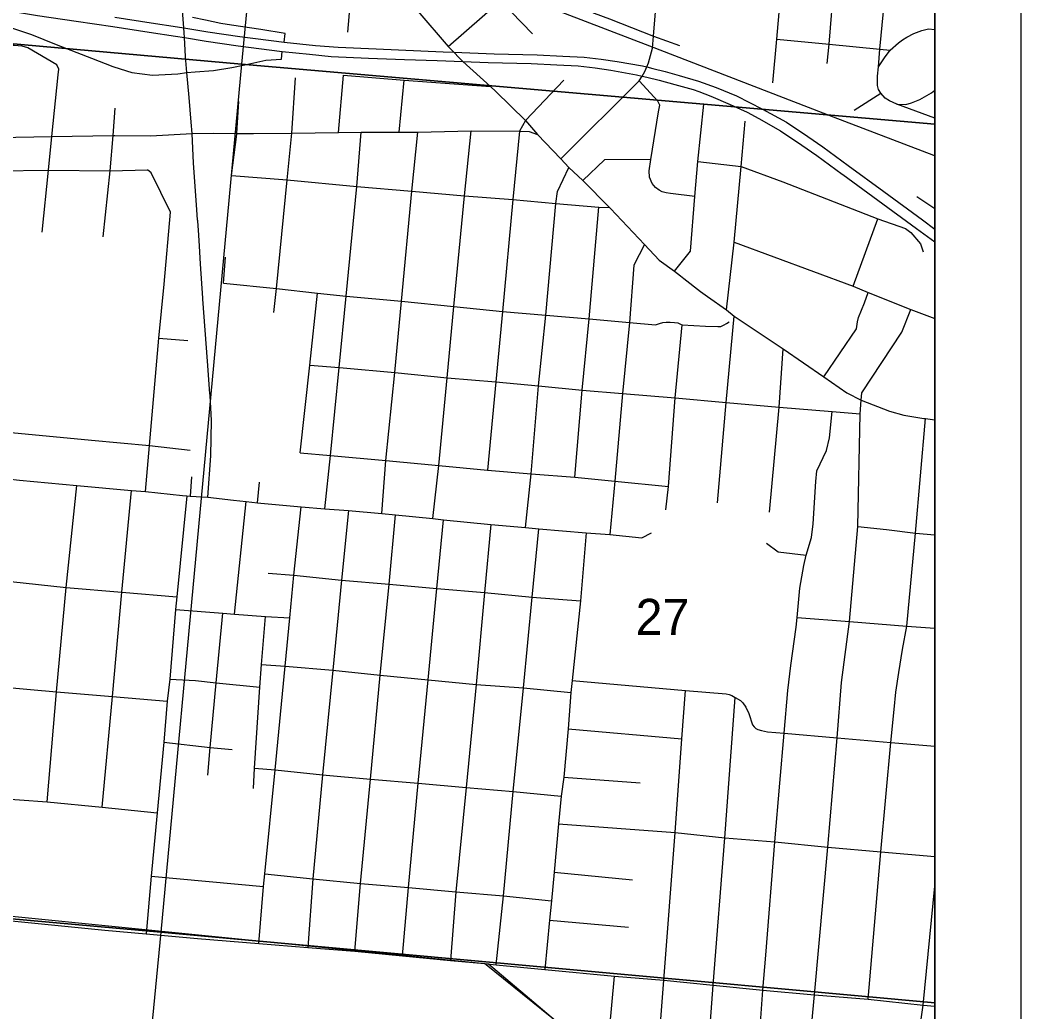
# Model space of a CAD drawing. Extents: x 0 to 34, y 0 to 22.
# Drawn here: x 7.838 to 9, y 16.794 to 17.945 of the extents above; entities that cross this region are included whole.
import ezdxf

# ---------------------------------------------------------------- set-up
doc = ezdxf.new("R2010")
doc.units = 0
for name, color, linetype in [('Default', 7, 'Continuous'), ('GM_X_City_Street', 7, 'Continuous'), ('GM_X_Interchange_Ramps', 7, 'Continuous'), ('GM_X_Rail_Line', 7, 'Continuous'), ('GM_X_Section', 7, 'Continuous'), ('GM_X_Section_Text', 7, 'Continuous'), ('GM_X_State_Route', 7, 'Continuous'), ('GM_X_Township_Road', 7, 'Continuous'), ('GM_X_US_Route', 7, 'Continuous'), ('SH_Data', 7, 'Continuous')]:
    doc.layers.add(name, color=color, linetype=linetype)

msp = doc.modelspace()

# ---------------------------------------------------------------- linework, layer by layer
at = {"layer": 'Default'}
for points in [[(8.9, 17.824), (8.9, 18.837), (8.1916, 18.9018), (8.0955, 17.8939)], [(8.9, 16.8048), (8.9, 17.824), (8.0955, 17.8939), (8.0016, 16.8868)], [(8.9, 15.7814), (8.9, 16.8048), (8.0016, 16.8868), (7.9035, 15.8736)]]:
    msp.add_lwpolyline(points, close=True, dxfattribs=at)
at = {"layer": 'GM_X_City_Street'}
for p, q in [((8.208, 17.8143), (8.2137, 17.8808)), ((8.2784, 17.815), (8.2841, 17.8753)), ((8.8063, 17.8402), (8.8375, 17.86)), ((8.0838, 17.7645), (8.0898, 17.8124)), ((8.293, 17.7464), (8.3, 17.815)), ((8.8792, 17.7402), (8.9, 17.7264)), ((8.8052, 17.636), (8.8337, 17.7144)), ((8.0746, 17.6398), (8.0767, 17.6697)), ((7.9994, 17.5759), (8.0332, 17.5733)), ((8.0372, 17.4151), (8.0357, 17.3925)), ((8.1138, 17.3849), (8.1161, 17.4089)), ((8.0874, 17.2557), (8.1006, 17.3863)), ((8.4745, 17.1225), (8.6063, 17.1111)), ((8.4693, 17.0668), (8.5579, 17.06)), ((8.7145, 16.9915), (8.7203, 17.0595)), ((8.7037, 16.8601), (8.7145, 16.9915)), ((7.9904, 16.9517), (8.1209, 16.9396)), ((8.4583, 16.9566), (8.5493, 16.9477)), ((8.8865, 16.8022), (8.9, 16.9403)), ((8.4529, 16.9008), (8.5445, 16.8926))]:
    msp.add_line(p, q, dxfattribs=at)
for points in [[(8.4658, 17.7839), (8.557, 17.8745), (8.5603, 17.8799), (8.5634, 17.8851), (8.5657, 17.8905), (8.5676, 17.8951), (8.5725, 17.9124), (8.5734, 17.9262), (8.5809, 18.0161), (8.5928, 18.1356), (8.5986, 18.1365), (8.6015, 18.1373), (8.6038, 18.1383), (8.6061, 18.1396), (8.6097, 18.1419), (8.612, 18.1444), (8.613, 18.1463), (8.6141, 18.1494), (8.6151, 18.1532), (8.6168, 18.164)], [(8.712, 17.8722), (8.7165, 17.9229), (8.7229, 17.994), (8.7276, 18.0443), (8.7323, 18.0974), (8.7371, 18.1527)], [(8.9, 17.8309), (8.8559, 17.8474), (8.8473, 17.851), (8.8424, 17.8541), (8.8375, 17.86), (8.8348, 17.8642), (8.8333, 17.8691), (8.8333, 17.8798), (8.8348, 17.8905), (8.836, 17.9113), (8.8432, 17.9829), (8.8457, 18.0185), (8.8462, 18.025), (8.8468, 18.0293), (8.8491, 18.0338), (8.8522, 18.038), (8.8567, 18.0417), (8.8624, 18.0448), (8.8734, 18.0465)], [(8.2186, 17.9307), (8.2215, 17.962), (8.2279, 18.0282)], [(8.032, 17.8842), (8.0305, 17.9026), (8.029, 17.9246), (8.0286, 17.9302), (8.0283, 17.936), (8.0274, 17.9511), (8.0268, 17.962), (8.0253, 17.9814), (8.023, 18.0144)], [(8.2373, 18.0182), (8.2468, 18.0082), (8.2986, 17.9567), (8.2999, 17.9553), (8.3352, 17.9144), (8.3416, 17.9076), (8.3479, 17.9009), (8.3524, 17.8968), (8.3843, 17.8677), (8.3905, 17.8621), (8.425, 17.8284), (8.4387, 17.812), (8.4658, 17.7839), (8.4754, 17.7739), (8.4916, 17.7589), (8.5224, 17.7275), (8.5237, 17.7263), (8.5629, 17.6847), (8.58, 17.6665), (8.598, 17.6535), (8.6049, 17.648)], [(8.7752, 17.8944), (8.7772, 17.9171), (8.7833, 17.9883)], [(8.3352, 17.9144), (8.3961, 17.9672), (8.4332, 17.9289)], [(8.4963, 17.959), (8.5045, 17.953), (8.5223, 17.9462), (8.5734, 17.9262), (8.6037, 17.9152)], [(7.8638, 17.6989), (7.8714, 17.7707), (7.8751, 17.8097), (7.8824, 17.8813), (7.8834, 17.8881), (7.8809, 17.893), (7.8472, 17.9126), (7.8408, 17.9145), (7.8315, 17.9155), (7.8271, 17.9155), (7.8227, 17.917), (7.8154, 17.9228), (7.8129, 17.9258)], [(8.8348, 17.8905), (8.8415, 17.901), (8.8483, 17.9099), (8.8577, 17.9184), (8.8623, 17.9218), (8.8675, 17.9252), (8.8758, 17.9294), (8.8848, 17.9328), (8.8926, 17.9346), (8.9, 17.9338)], [(8.7165, 17.9229), (8.7772, 17.9171), (8.836, 17.9113), (8.8483, 17.9099)], [(8.038, 17.8134), (8.037, 17.8264), (8.0347, 17.855), (8.032, 17.8842)], [(8.2137, 17.8808), (8.2841, 17.8753), (8.3843, 17.8677)], [(8.133, 17.6055), (8.1358, 17.6333), (8.1483, 17.7596), (8.1536, 17.8135), (8.158, 17.878)], [(8.4693, 17.875), (8.425, 17.8284), (8.4178, 17.8161), (8.4104, 17.7368), (8.3983, 17.6069), (8.3904, 17.5254), (8.381, 17.4229)], [(8.6216, 17.7404), (8.5933, 17.7435), (8.5883, 17.7443), (8.5837, 17.7455), (8.5802, 17.7474), (8.576, 17.7505), (8.5721, 17.7551), (8.569, 17.7628), (8.5686, 17.7698), (8.5705, 17.7833), (8.5794, 17.8386), (8.5808, 17.8461), (8.5787, 17.8509), (8.557, 17.8745)], [(8.8559, 17.8474), (8.8664, 17.847), (8.873, 17.849), (8.8827, 17.8529), (8.8961, 17.8604), (8.9, 17.8634)], [(8.0898, 17.8124), (8.0899, 17.8134), (8.0923, 17.8505)], [(8.598, 17.6535), (8.6164, 17.6766), (8.6216, 17.7404), (8.6251, 17.7807), (8.632, 17.8474)], [(7.9347, 17.6935), (7.9428, 17.7701), (7.9464, 17.8109), (7.9489, 17.8426)], [(8.6582, 17.6086), (8.667, 17.6874), (8.6753, 17.775), (8.6797, 17.8276)], [(7.7182, 17.8078), (7.7277, 17.808), (7.7409, 17.8083), (7.8054, 17.8088), (7.812, 17.8088), (7.8751, 17.8097), (7.9464, 17.8109), (7.9484, 17.8109)], [(7.9484, 17.8109), (7.9898, 17.8107), (8.038, 17.8134), (8.0634, 17.8135), (8.0899, 17.8134), (8.098, 17.8133)], [(8.0444, 17.713), (8.043, 17.7307), (8.0396, 17.779), (8.038, 17.8134)], [(8.098, 17.8133), (8.1091, 17.8132), (8.1536, 17.8135), (8.208, 17.8143), (8.2344, 17.8147), (8.2784, 17.815), (8.3, 17.815), (8.3617, 17.8163), (8.4178, 17.8161), (8.4291, 17.8158), (8.4387, 17.812)], [(8.2086, 17.5419), (8.2167, 17.6245), (8.2292, 17.7517), (8.2344, 17.8147)], [(8.3175, 17.3665), (8.3244, 17.428), (8.3342, 17.53), (8.3417, 17.6127), (8.3542, 17.7409), (8.3617, 17.8163)], [(8.5705, 17.7833), (8.5165, 17.7826), (8.4916, 17.7589)], [(8.6251, 17.7807), (8.6753, 17.775), (8.7236, 17.7571), (8.8337, 17.7144), (8.8658, 17.7031), (8.872, 17.6984), (8.8833, 17.6853), (8.8863, 17.6762)], [(7.1731, 17.6598), (7.207, 17.6858), (7.2406, 17.7105), (7.3207, 17.7132), (7.4116, 17.7144), (7.499, 17.7158), (7.568, 17.7076), (7.6318, 17.7023), (7.7067, 17.6964), (7.7185, 17.7023), (7.8124, 17.7701), (7.8714, 17.7707), (7.9428, 17.7701), (7.9864, 17.7713)], [(7.984, 17.3979), (7.9884, 17.4512), (7.9994, 17.5759), (8.0054, 17.6386), (8.0131, 17.722), (7.9904, 17.7676), (7.9864, 17.7713)], [(8.0838, 17.7645), (8.1483, 17.7596), (8.2292, 17.7517), (8.293, 17.7464), (8.3542, 17.7409), (8.4104, 17.7368), (8.4603, 17.732), (8.5101, 17.7279), (8.5224, 17.7275)], [(8.425, 17.3561), (8.4314, 17.4183), (8.44, 17.5207), (8.4486, 17.6027), (8.4603, 17.732), (8.4619, 17.7461), (8.4754, 17.7739)], [(8.2581, 17.3723), (8.263, 17.4341), (8.2733, 17.536), (8.2809, 17.6188), (8.293, 17.7464)], [(8.4821, 17.4146), (8.4908, 17.5155), (8.4988, 17.5982), (8.5101, 17.7279)], [(8.0465, 17.6826), (8.0457, 17.6953), (8.0445, 17.7121), (8.0444, 17.713)], [(8.0505, 17.6223), (8.0478, 17.662), (8.0465, 17.6826)], [(8.5629, 17.6847), (8.5507, 17.6604), (8.5457, 17.5939), (8.5376, 17.5118), (8.5286, 17.4101), (8.5227, 17.348)], [(8.667, 17.6874), (8.8052, 17.636), (8.8226, 17.629), (8.8723, 17.6093), (8.9, 17.5986)], [(8.6049, 17.648), (8.6088, 17.6449), (8.628, 17.63), (8.636, 17.6243)], [(8.0746, 17.6398), (8.1358, 17.6333), (8.1834, 17.6281), (8.2167, 17.6245), (8.2809, 17.6188), (8.3417, 17.6127), (8.3983, 17.6069), (8.4486, 17.6027), (8.4988, 17.5982), (8.5457, 17.5939), (8.5758, 17.5912), (8.5805, 17.5927), (8.5844, 17.5939), (8.5883, 17.5944), (8.5929, 17.5946), (8.5977, 17.5942), (8.6017, 17.5935), (8.6049, 17.5922), (8.6069, 17.5912), (8.6338, 17.5897), (8.6481, 17.5894), (8.6516, 17.5895), (8.6554, 17.5912), (8.6584, 17.5927), (8.6612, 17.595)], [(8.1634, 17.4428), (8.1746, 17.5445), (8.1834, 17.6281)], [(8.636, 17.6243), (8.6582, 17.6086), (8.6672, 17.6015), (8.6753, 17.596)], [(8.771, 17.5309), (8.8091, 17.5867), (8.8102, 17.595), (8.8115, 17.5998), (8.8182, 17.617), (8.8226, 17.629)], [(8.0587, 17.5116), (8.0559, 17.549), (8.0506, 17.6212), (8.0505, 17.6223)], [(8.6477, 17.3849), (8.658, 17.5013), (8.6672, 17.6015)], [(8.9, 16.4865), (8.8662, 16.4889), (8.8359, 16.4923), (8.7983, 16.5429), (8.7412, 16.6234), (8.751, 16.6985), (8.7551, 16.7564), (8.7604, 16.814), (8.776, 16.9853), (8.7868, 17.1123), (8.7916, 17.1766), (8.8011, 17.2471), (8.8108, 17.3575), (8.8134, 17.4882), (8.8144, 17.504), (8.8153, 17.5125), (8.8617, 17.5828), (8.8723, 17.6093)], [(8.5877, 17.3766), (8.591, 17.4037), (8.5986, 17.5068), (8.6069, 17.5912)], [(8.6753, 17.596), (8.724, 17.5635), (8.771, 17.5309), (8.7979, 17.5126), (8.8144, 17.504), (8.8475, 17.491), (8.8639, 17.4867), (8.8874, 17.4828)], [(8.708, 17.374), (8.7194, 17.4958), (8.724, 17.5635)], [(8.1746, 17.5445), (8.2086, 17.5419), (8.2135, 17.5414)], [(8.1921, 17.378), (8.1986, 17.4396), (8.2086, 17.5419)], [(8.2135, 17.5414), (8.2733, 17.536), (8.3342, 17.53), (8.3904, 17.5254), (8.44, 17.5207), (8.4908, 17.5155), (8.5376, 17.5118), (8.5986, 17.5068), (8.658, 17.5013), (8.7194, 17.4958), (8.7807, 17.4908), (8.8134, 17.4882)], [(8.0564, 17.3913), (8.0597, 17.4393), (8.0607, 17.4804), (8.0588, 17.5095), (8.0587, 17.5116)], [(7.613, 17.4851), (7.7167, 17.4762), (7.8282, 17.4663), (7.9213, 17.4577), (7.9884, 17.4512), (8.0357, 17.4461)], [(8.7203, 17.0595), (8.7252, 17.1178), (8.7295, 17.1671), (8.7327, 17.196), (8.7392, 17.2406), (8.7402, 17.2517), (8.7435, 17.2859), (8.7479, 17.3123), (8.7505, 17.324), (8.7567, 17.3445), (8.7588, 17.3606), (8.7618, 17.4097), (8.7632, 17.4221), (8.7742, 17.4455), (8.7779, 17.4602), (8.7807, 17.4908)], [(8.8226, 16.8089), (8.8373, 16.9799), (8.849, 17.1067), (8.8528, 17.145), (8.8548, 17.1654), (8.8584, 17.1881), (8.8624, 17.2149), (8.8677, 17.2419), (8.8775, 17.3498), (8.8893, 17.4825)], [(8.8874, 17.4828), (8.8893, 17.4825), (8.9, 17.481)], [(7.3271, 17.4595), (7.3398, 17.4568), (7.4144, 17.4515), (7.4756, 17.4469), (7.4803, 17.4464), (7.5437, 17.4399), (7.6073, 17.4333), (7.628, 17.4313), (7.695, 17.4246), (7.7123, 17.423), (7.7746, 17.417), (7.8046, 17.4146), (7.8242, 17.4125), (7.8376, 17.411), (7.9042, 17.4049), (7.9675, 17.3993), (7.984, 17.3979), (8.0267, 17.3935)], [(8.1634, 17.4428), (8.1986, 17.4396), (8.263, 17.4341), (8.3244, 17.428), (8.381, 17.4229), (8.4314, 17.4183), (8.4821, 17.4146), (8.5286, 17.4101), (8.591, 17.4037)], [(7.8699, 17.0379), (7.8806, 17.1657), (7.8918, 17.2868), (7.9042, 17.4049)], [(7.9337, 17.032), (7.9456, 17.1601), (7.9566, 17.2811), (7.9675, 17.3993)], [(8.0318, 17.393), (8.0201, 17.2757), (8.0187, 17.2613), (8.0121, 17.1803), (8.0091, 17.1548), (8.0053, 17.1074), (7.9974, 17.0251), (7.9904, 16.9517), (7.9846, 16.8849)], [(8.0267, 17.3935), (8.0318, 17.393), (8.0357, 17.3925), (8.0564, 17.3913), (8.0859, 17.3879), (8.1006, 17.3863), (8.1138, 17.3849), (8.1178, 17.3845)], [(8.1154, 16.8737), (8.1209, 16.9396), (8.1224, 16.9545), (8.1343, 17.0751), (8.1462, 17.1955), (8.1514, 17.2513), (8.156, 17.301), (8.1645, 17.3801)], [(8.1178, 17.3845), (8.1432, 17.3823), (8.1645, 17.3801), (8.1921, 17.378), (8.2196, 17.376), (8.2581, 17.3723), (8.274, 17.3708), (8.3175, 17.3665), (8.3297, 17.3651), (8.3846, 17.3599), (8.425, 17.3561), (8.4403, 17.3548)], [(8.2196, 17.376), (8.2115, 17.2953), (8.2013, 17.1908), (8.1895, 17.0695), (8.178, 16.9486), (8.1725, 16.869)], [(8.2267, 16.8647), (8.2336, 16.9433), (8.2451, 17.0642), (8.2564, 17.1849), (8.2669, 17.2905), (8.274, 17.3708)], [(8.2821, 16.8594), (8.289, 16.9388), (8.3005, 17.0595), (8.3119, 17.1795), (8.3221, 17.2855), (8.3297, 17.3651)], [(8.3846, 17.3599), (8.3775, 17.2809), (8.3675, 17.1741), (8.3561, 17.0547), (8.3442, 16.9337), (8.3379, 16.8541)], [(8.8108, 17.3575), (8.8441, 17.3539), (8.8775, 17.3498), (8.9, 17.3478)], [(8.391, 16.849), (8.3996, 16.9291), (8.4107, 17.0498), (8.4227, 17.1703), (8.4328, 17.2756), (8.4403, 17.3548)], [(8.4403, 17.3548), (8.4955, 17.35), (8.5227, 17.348), (8.5599, 17.3443), (8.5712, 17.35)], [(8.4955, 17.35), (8.4886, 17.271), (8.479, 17.1788), (8.4775, 17.1648), (8.4745, 17.1225), (8.4693, 17.0668), (8.4663, 17.0446), (8.4633, 17.0124), (8.4583, 16.9566), (8.4551, 16.9232), (8.4529, 16.9008), (8.4474, 16.8436)], [(8.7047, 17.3379), (8.7182, 17.3279), (8.7505, 17.324)], [(7.5802, 17.316), (7.6167, 17.3127), (7.6852, 17.3067), (7.7635, 17.2999), (7.8275, 17.2937), (7.8918, 17.2868), (7.9566, 17.2811), (8.0201, 17.2757)], [(8.1261, 17.3034), (8.156, 17.301), (8.2115, 17.2953), (8.2669, 17.2905), (8.3221, 17.2855), (8.3775, 17.2809), (8.4328, 17.2756), (8.4886, 17.271)], [(8.0187, 17.2613), (8.0735, 17.2569), (8.0874, 17.2557), (8.1231, 17.2531), (8.1514, 17.2513)], [(8.0561, 17.0689), (8.0589, 17.1012), (8.0659, 17.176), (8.0735, 17.2569)], [(8.1091, 17.0535), (8.1106, 17.0772), (8.1166, 17.1712), (8.1187, 17.1975), (8.1231, 17.2531)], [(8.7402, 17.2517), (8.8011, 17.2471), (8.8677, 17.2419), (8.9, 17.2395)], [(8.1187, 17.1975), (8.1462, 17.1955), (8.2013, 17.1908), (8.2564, 17.1849), (8.3119, 17.1795), (8.3675, 17.1741), (8.4227, 17.1703), (8.4775, 17.1648)], [(7.7528, 17.1769), (7.8162, 17.1716), (7.8806, 17.1657), (7.9456, 17.1601), (8.0091, 17.1548)], [(8.0121, 17.1803), (8.0421, 17.1786), (8.0659, 17.176), (8.1166, 17.1712)], [(8.479, 17.1788), (8.6106, 17.167), (8.6579, 17.1632), (8.6615, 17.1626), (8.6643, 17.1615), (8.6684, 17.1592), (8.6743, 17.1555), (8.6771, 17.1527), (8.6807, 17.1478), (8.684, 17.1403), (8.6885, 17.1273), (8.6902, 17.1249), (8.6921, 17.1232), (8.6947, 17.1219), (8.6989, 17.1206), (8.7058, 17.1191), (8.7252, 17.1178), (8.7868, 17.1123), (8.849, 17.1067), (8.9, 17.1026)], [(8.5554, 16.7041), (8.5774, 16.726), (8.5855, 16.8312), (8.5988, 17.0025), (8.6063, 17.1111), (8.6106, 17.167)], [(8.6116, 16.6556), (8.6318, 16.6797), (8.6429, 16.8253), (8.6561, 16.9964), (8.6684, 17.1592)], [(8.0053, 17.1074), (8.0589, 17.1012), (8.0846, 17.0986)], [(8.1106, 17.0772), (8.1343, 17.0751), (8.1895, 17.0695), (8.2451, 17.0642), (8.3005, 17.0595), (8.3561, 17.0547), (8.4107, 17.0498), (8.4663, 17.0446)], [(7.742, 17.049), (7.8053, 17.0427), (7.8699, 17.0379), (7.9337, 17.032), (7.9974, 17.0251)], [(8.4633, 17.0124), (8.5988, 17.0025), (8.6561, 16.9964), (8.7145, 16.9915), (8.776, 16.9853), (8.8373, 16.9799), (8.9, 16.9744)], [(8.1224, 16.9545), (8.178, 16.9486), (8.2336, 16.9433), (8.289, 16.9388), (8.3442, 16.9337), (8.3996, 16.9291), (8.4551, 16.9232)], [(7.8169, 16.901), (7.9368, 16.8891), (7.9846, 16.8849), (8.0444, 16.8796), (8.1154, 16.8737), (8.1725, 16.869), (8.2267, 16.8647), (8.2821, 16.8594), (8.3379, 16.8541), (8.3773, 16.8503), (8.391, 16.849)], [(8.6978, 16.7817), (8.7003, 16.8196), (8.7037, 16.8601)], [(8.8838, 16.33), (8.8824, 16.3315), (8.8656, 16.3492), (8.8164, 16.4162), (8.7823, 16.464), (8.7583, 16.4972), (8.6994, 16.5756), (8.6873, 16.59), (8.6771, 16.5987), (8.667, 16.6073), (8.6336, 16.6362), (8.6116, 16.6556), (8.5992, 16.6662), (8.5554, 16.7041), (8.538, 16.7187), (8.5006, 16.7499), (8.4555, 16.7875), (8.3773, 16.8503)], [(8.391, 16.849), (8.4474, 16.8436), (8.5281, 16.8359), (8.5855, 16.8312), (8.6429, 16.8253), (8.7003, 16.8196), (8.7604, 16.814), (8.8226, 16.8089), (8.8865, 16.8022), (8.9, 16.801)], [(8.5006, 16.7499), (8.5224, 16.7729), (8.5281, 16.8359)], [(8.7583, 16.4972), (8.784, 16.5233), (8.7983, 16.5429), (8.8163, 16.5712), (8.8327, 16.6043), (8.844, 16.6316), (8.861, 16.6738), (8.8646, 16.6881), (8.8784, 16.7457), (8.8865, 16.8022)]]:
    msp.add_lwpolyline(points, dxfattribs=at)
at = {"layer": 'GM_X_Interchange_Ramps'}
for points in [[(7.7529, 17.9657), (7.7518, 17.9556), (7.7673, 17.9524), (7.7864, 17.9477), (7.8064, 17.9422), (7.8295, 17.9356), (7.8515, 17.928), (7.8804, 17.9167), (7.9213, 17.9005), (7.946, 17.891), (7.947, 17.8907)], [(8.1448, 17.9194), (8.1459, 17.9293), (8.1179, 17.934), (8.0836, 17.939), (8.0713, 17.941), (8.0535, 17.9448), (8.0384, 17.9479)], [(8.032, 17.8842), (8.0415, 17.885), (8.063, 17.8864), (8.084, 17.8897), (8.0992, 17.8931), (8.1234, 17.8984), (8.1416, 17.8994), (8.1427, 17.9084)], [(7.947, 17.8907), (7.968, 17.8842), (7.9922, 17.8811), (8.0215, 17.8826), (8.032, 17.8842)]]:
    msp.add_lwpolyline(points, dxfattribs=at)
at = {"layer": 'GM_X_Rail_Line'}
for points in [[(8.3965, 17.9816), (8.5687, 17.9149), (8.7821, 17.8328), (8.8983, 17.7883), (8.9, 17.7876)], [(8.9, 16.3116), (8.8798, 16.3324), (8.6781, 16.5996), (8.3819, 16.8496), (7.8287, 16.9051), (7.8169, 16.8999)]]:
    msp.add_lwpolyline(points, dxfattribs=at)
at = {"layer": 'GM_X_Section'}
for points in [[(7.1919, 18.9909), (8.1916, 18.9018), (8.0955, 17.8939), (7.0966, 17.983)], [(7.0966, 17.983), (8.0955, 17.8939), (8.0016, 16.8868), (7.0031, 16.9763)], [(7.0031, 16.9763), (8.0016, 16.8868), (7.9035, 15.8736), (6.9063, 15.9571)]]:
    msp.add_lwpolyline(points, close=True, dxfattribs=at)
at = {"layer": 'GM_X_State_Route'}
msp.add_lwpolyline([(8.9, 15.5977), (8.9, 20.2522)], dxfattribs=at)
at = {"layer": 'GM_X_Township_Road'}
msp.add_lwpolyline([(8.9, 14.1), (8.9, 20.9)], dxfattribs=at)
at = {"layer": 'GM_X_US_Route'}
for points in [[(7.7529, 17.9657), (7.8026, 17.9594), (7.8584, 17.9503), (7.9036, 17.9436), (7.9461, 17.9373), (7.9883, 17.9307), (8.0188, 17.9263), (8.029, 17.9246), (8.0543, 17.9204), (8.0913, 17.9148), (8.1427, 17.9084), (8.1741, 17.9054), (8.1994, 17.9028), (8.2428, 17.9006), (8.2846, 17.8992)], [(7.9482, 17.9483), (7.9904, 17.9417), (8.0209, 17.9372), (8.0283, 17.936), (8.0564, 17.9313), (8.0934, 17.9257), (8.1448, 17.9194), (8.1811, 17.9155), (8.2077, 17.9135), (8.2518, 17.9115), (8.3293, 17.9081), (8.3416, 17.9076), (8.3885, 17.9058), (8.4385, 17.9045), (8.4683, 17.903), (8.493, 17.9017), (8.5127, 17.8995), (8.5312, 17.8969), (8.5608, 17.8917), (8.5657, 17.8905), (8.5729, 17.8887), (8.5871, 17.8851), (8.6032, 17.8807), (8.6256, 17.8739), (8.6461, 17.8665), (8.6697, 17.8569), (8.7001, 17.8415), (8.7279, 17.8263), (8.7526, 17.8099), (8.77, 17.7979), (8.7996, 17.7763), (8.8407, 17.7462), (8.8856, 17.7132), (8.9, 17.7025)], [(8.2846, 17.8992), (8.3223, 17.898), (8.3524, 17.8968), (8.3815, 17.8957), (8.4315, 17.8944), (8.4613, 17.8929), (8.4859, 17.8916), (8.5057, 17.8894), (8.5241, 17.8868), (8.5537, 17.8815), (8.5603, 17.8799), (8.5659, 17.8786), (8.58, 17.875), (8.5981, 17.87), (8.6196, 17.8644), (8.6262, 17.862)], [(8.6262, 17.862), (8.6402, 17.8567), (8.6626, 17.8468), (8.6822, 17.8381), (8.6958, 17.8306), (8.7209, 17.8162), (8.7455, 17.7998), (8.763, 17.7878), (8.7926, 17.7662), (8.7934, 17.7656)], [(8.7934, 17.7656), (8.8337, 17.7361), (8.8786, 17.7031), (8.9, 17.6876)]]:
    msp.add_lwpolyline(points, dxfattribs=at)
at = {"layer": 'SH_Data'}
for p, q in [((9, 21), (9, 14)), ((8.9, 20.9), (8.9, 14.1))]:
    msp.add_line(p, q, dxfattribs=at)

# ---------------------------------------------------------------- texts
at = {"layer": 'GM_X_Section_Text'}
msp.add_text('27', height=0.04186, rotation=0, dxfattribs=at).set_placement((8.5528, 17.2316))

doc.saveas('drawing.dxf')
